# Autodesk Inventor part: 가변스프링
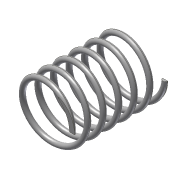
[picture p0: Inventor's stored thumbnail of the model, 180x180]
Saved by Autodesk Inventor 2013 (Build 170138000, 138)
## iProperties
Created: 2018-06
Part Number: 가변스프링
Material: 강철, 연강
Document SubType Name: Modeling
Designer: Administrator
Density: 7.86 g/cm^3
Mass: 82.8002 g
Surface Area: 106.473 cm^2
Volume: 10.5344 cm^3
Author: Administrator
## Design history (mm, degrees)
sketch "스케치1"
  geometry: L1 (0, 0)-(0, 73.25); L2 (0, 73.25)-(22.5, 73.25); C1 r 2 at (22.5, 0)
  constraints: 4 end point, 1 centre point, 1 horizontal alignment, 1 perpendicular, 1 vertical, 1 vertical alignment
  dimensions: "d0" = 73.25 distance of L1.start L1.end (derived); "d1" = 22.5 distance of L1.end L2.end; "d2" = 4 diameter of C1
feature "코일1" sketch "스케치1" pitch "d3" = 10; turns "d5" = 6; dims "d4" = 73.24997 (computed from d0), "d6" = 0, angle "d7" = 90 deg, angle "d8" = 90 deg, "d9" = 0, "d10" = 0
sketch "스케치2"
  geometry: L1 (-40, 0)-(40, 0); L2 (40, 0)-(40, 73.25); L3 (40, 73.25)-(-40, 73.25); L4 (-40, 73.25)-(-40, 0); 2 further points
  constraints: 8 end point, 2 parallel, 1 coincident, 1 horizontal, 1 horizontal alignment, 1 midpoint, 1 perpendicular
  dimensions: "d11" = 73.24997 distance of L3.end L1.start (derived); "d13" = 80 distance of L2.end L3.end
extrude "돌출1" sketch "스케치2" stored distance "d14" = 80 (= d13); taper "d15" = 0 deg
node "솔리드1"
